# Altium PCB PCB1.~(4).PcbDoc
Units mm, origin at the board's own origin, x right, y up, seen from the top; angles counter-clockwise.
Board outline 152.4 x 101.6 mm, 2 copper layers (Top Layer, Bottom Layer); 19 components, 17 nets, 64 pads, 0 vias.
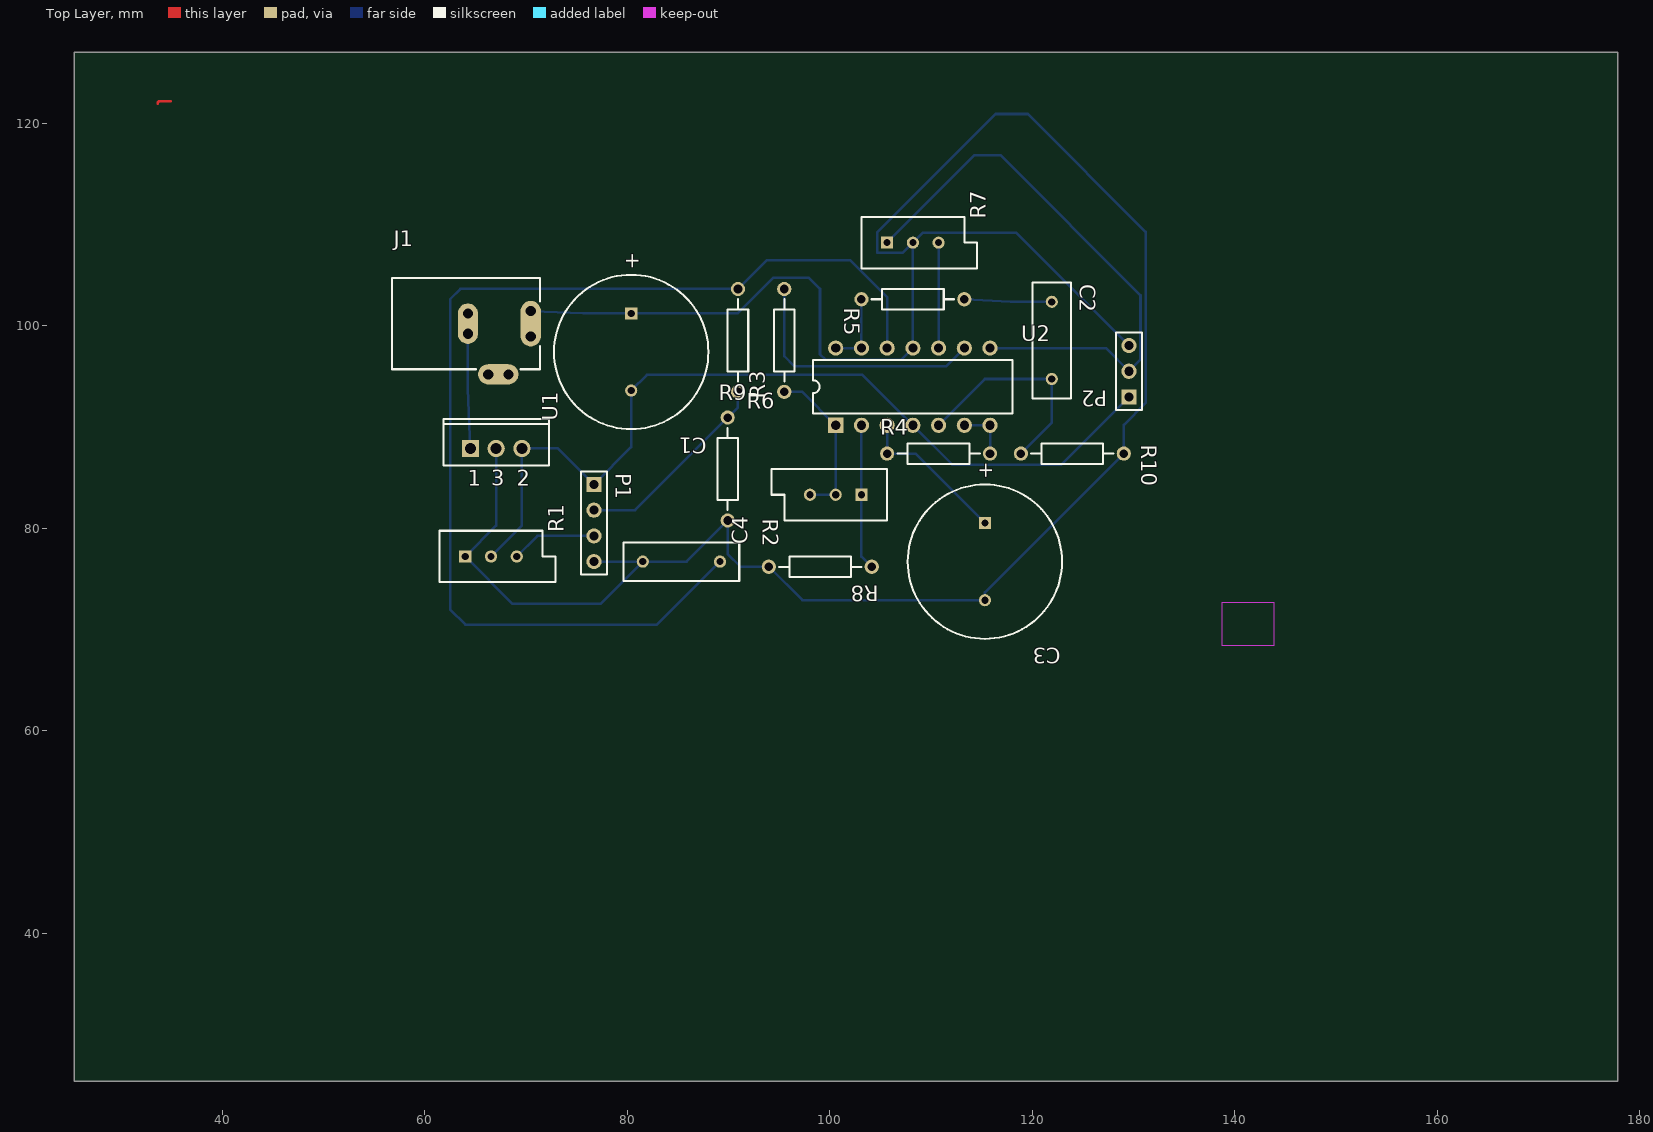
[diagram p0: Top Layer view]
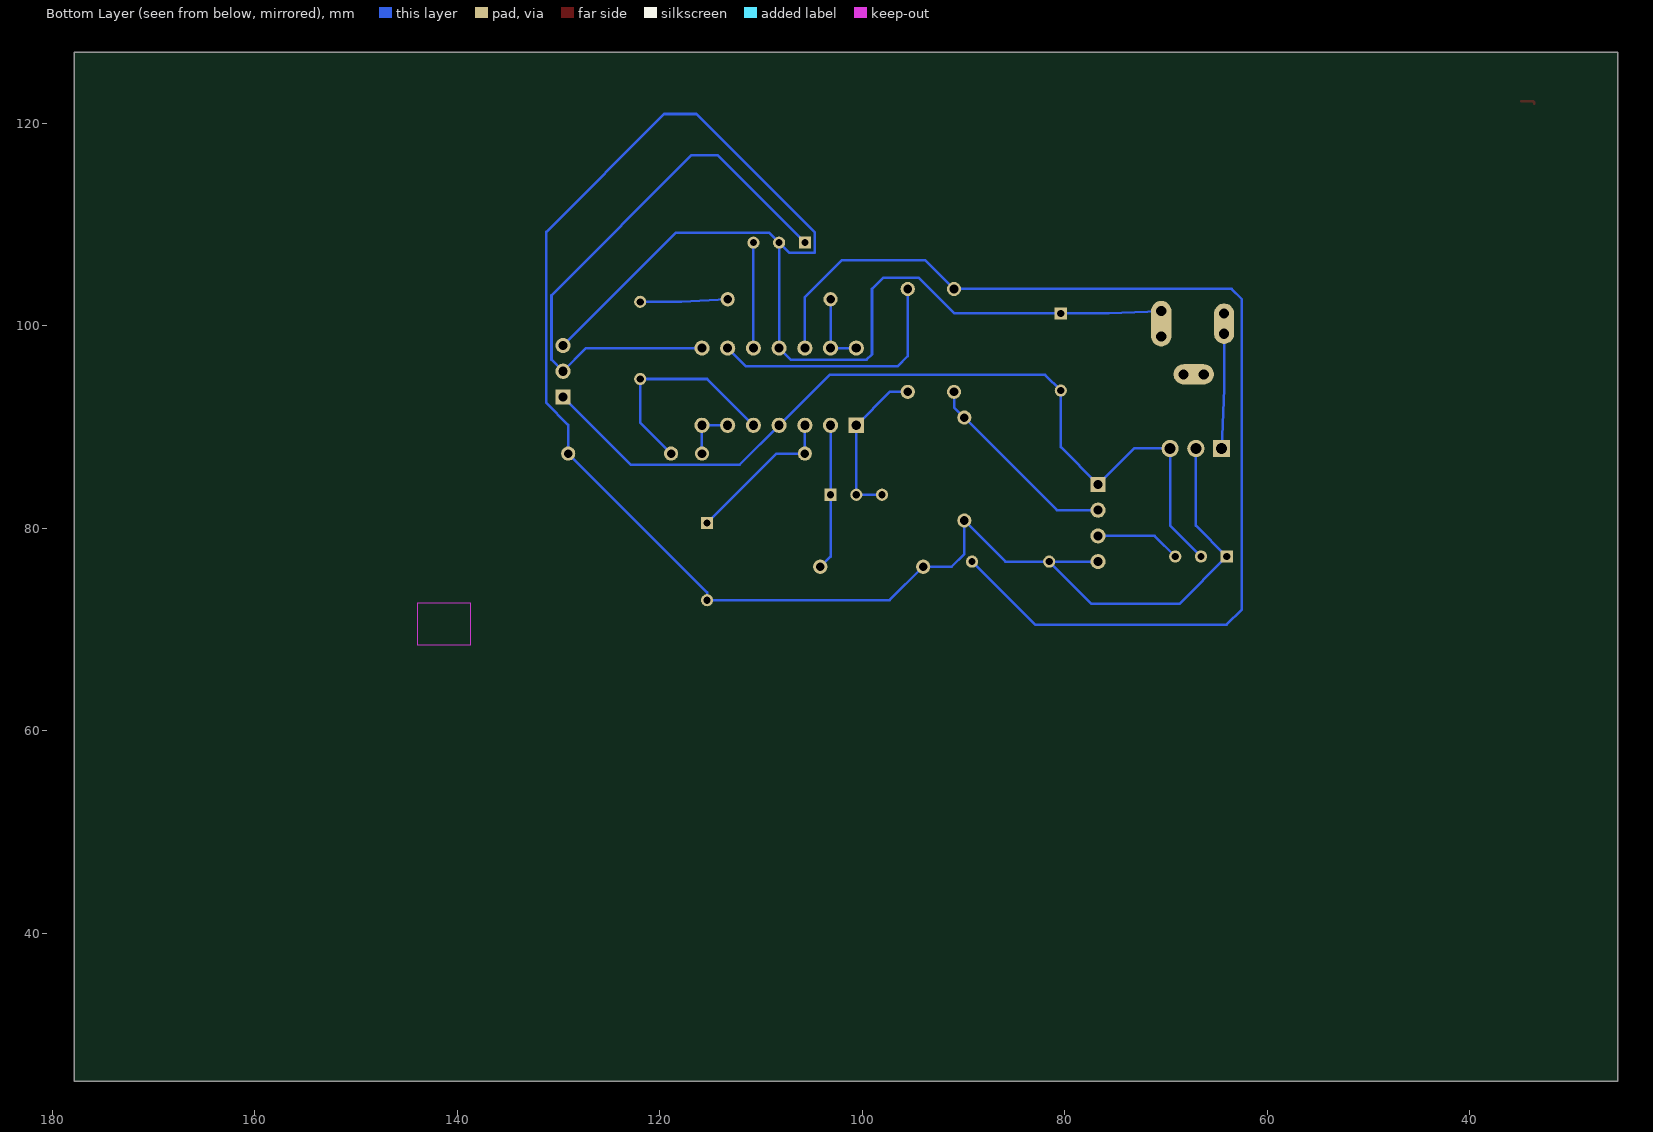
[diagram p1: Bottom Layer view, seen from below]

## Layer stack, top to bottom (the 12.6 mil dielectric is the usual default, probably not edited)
Top Layer: signal copper 0.0356
Dielectric: dielectric 0.32, FR-4, Dk 4.8
Bottom Layer: signal copper 0.0356

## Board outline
25.4,25.4 177.8,25.4 177.8,127 25.4,127

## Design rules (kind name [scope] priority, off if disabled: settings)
Clearance [All] p1: gap=0.254
ComponentClearance [All] p1: gap=0.254 collisioncheckmode=3 verticalgap=0.254
PolygonConnect [All] p1: connectstyle=Relief reliefconductorwidth=0.254 reliefentries=4 polygonreliefangle="90 Angle"
RoomDefinition Sheet1 [InComponentClass('Sheet1')] p1: confinementstyle=ConfineIn formatcopy=TRUE lockcomponents=FALSE outline 51.181,58.42 157.734,58.42 157.734,111.633 51.181,111.633
RoutingVias [All] p1: holewidth=0.711 width=1.27 viastyle="Through Hole" minholewidth=0.711 minwidth=1.27 maxholewidth=0.711 maxwidth=1.27
SolderMaskExpansion [All] p1: expansion=0.102
TestPointUsage [All] p1: valid=0 allowmultiple=FALSE
Testpoint [All] p1: side=15 testpointundercomponent=TRUE minsize=1.016 maxsize=2.54 preferedsize=1.524 minholesize=0 maxholesize=1.016 preferedholesize=0.813 testpointgrid=0.025 style=1023 order=0123456789
Width [All] p1: maxlimit=0.254 minlimit=0.254 preferedwidth=0.254
18 further rules are at their usual default settings.

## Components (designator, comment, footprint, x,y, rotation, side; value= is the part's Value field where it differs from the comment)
C1 "Cap Pol1" RB7.6-15 80.391,97.409 r90 top
C2 "Cap" RAD-0.3 121.92,98.552 r90 top
C3 "Cap Pol1" RB7.6-15 115.316,76.708 r90 top
C4 "Cap" RAD-0.3 85.344,76.708 r0 top
J1 "PWR2.5" KLD-0202 56.769,100.203 r0 top
P1 "Header 4" HDR1X4 76.708,84.328 r270 top
P2 "Header 3" HDR1X3 129.54,92.964 r90 top
R1 "RPot" VR5 66.548,77.216 r0 top
R2 "RPot" VR5 100.584,83.312 r180 top
R3 "Res2" AXIAL-0.4 95.504,98.552 r270 top
R4 "Res2" AXIAL-0.4 110.744,87.376 r0 top
R5 "Res2" AXIAL-0.4 108.204,102.616 r180 top
R6 "Res2" AXIAL-0.4 90.932,98.552 r270 top
R7 "RPot" VR5 108.204,108.204 r0 top
R8 "Res2" AXIAL-0.4 99.06,76.2 r180 top
R9 "Res2" AXIAL-0.4 89.916,85.852 r90 top
R10 "Res2" AXIAL-0.4 123.952,87.376 r0 top
U1 "L7812ABV" TO220ABN 67.056,87.884 r0 top
U2 "LM324AN" N14A 108.204,93.98 r0 top

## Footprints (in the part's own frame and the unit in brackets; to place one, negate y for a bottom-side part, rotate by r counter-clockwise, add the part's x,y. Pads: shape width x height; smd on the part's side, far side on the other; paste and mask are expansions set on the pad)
AXIAL-0.4 [mm] "Resistor; 2 Leads"
  round 1.4 hole 0.85: 1(-5.08,0) 2(5.08,0)
  silkscreen extent -4.06,-1.02 4.06,1.02
HDR1X3 [mm] "Connector; Header; 3 Position"
  rect 1.5x1.5 hole 0.9: 1(0,0)
  round 1.5 hole 0.9: 2(2.54,0) 3(5.08,0)
  silkscreen extent -1.27,-1.27 6.35,1.27
HDR1X4 [mm] "Connector; Header; 4 Position"
  rect 1.5x1.5 hole 0.9: 1(0,0)
  round 1.5 hole 0.9: 2(2.54,0) 3(5.08,0) 4(7.62,0)
  silkscreen extent -1.27,-1.27 8.89,1.27
KLD-0202 [mm] "DC Power Jack, 2.5mm, KLD Series, PCB Mount"
  oval 2x4.5 all layers, no hole: 1(13.7,0)
  round 1.5 hole 1: 1A(13.7,-1.25) 1B(13.7,1.25) 2A(7.5,-1) 2B(7.5,1) 3A(9.5,-5) 3B(11.5,-5)
  oval 2x4 all layers, no hole: 2(7.5,0)
  oval 4x2 all layers, no hole: 3(10.5,-5)
  silkscreen extent 0,-4.5 14.6,4.5
N14A [mm] "DIP; 14 Leads; Row Spacing 7.62 mm; Pitch 2.54 mm"
  rect 1.5x1.5 hole 0.9: 1(-7.62,-3.81)
  round 1.5 hole 0.9: 2(-5.08,-3.81) 3(-2.54,-3.81) 4(0,-3.81) 5(2.54,-3.81) 6(5.08,-3.81) 7(7.62,-3.81) 8(7.62,3.81) 9(5.08,3.81) 10(2.54,3.81) 11(0,3.81) 12(-2.54,3.81) 13(-5.08,3.81) 14(-7.62,3.81)
  silkscreen extent -9.85,-2.65 9.85,2.65
RAD-0.3 [mm] "Capacitor; 2 Leads"
  round 1.2 hole 0.7: 1(-3.81,0) 2(3.81,0)
  silkscreen extent -5.71,-1.91 5.71,1.91
RB7.6-15 [mm] "Polarized Capacitor (Radial); 2 Leads"
  rect 1.2x1.2 hole 0.7: 1(3.81,0)
  round 1.2 hole 0.7: 2(-3.81,0)
  silkscreen extent -7.62,-7.62 7.62,7.62
TO220ABN [mm] "TO, Thru-Hole, Vertical, Heatsink Mounted; 3 In-Line Leads; Pitch 2.54 mm; Pin sequence 1, 3, 2"
  rect 1.7x1.7 hole 1.1: 1(-2.54,0)
  round 1.7 hole 1.1: 2(2.54,0) 3(0,0)
  silkscreen extent -5.2,-1.7 5.2,2.9
VR5 [mm] "Potentiometer; 3 Leads"
  rect 1.2x1.2 hole 0.7: 1(-2.54,0)
  round 1.2 hole 0.7: 2(0,0) 3(2.54,0)
  silkscreen extent -5.08,-2.54 6.35,2.54

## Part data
C1 C3: "Polarized Capacitor (Radial)"
C2 C4: "Capacitor"
J1: "Low Voltage Power Supply Connector"
P1: "Header, 4-Pin"
P2: library part "Header 2", "Header, 2-Pin"
R1 R2 R7: "Potentiometer"
R3 R4 R5 R6 R8 R9 R10: "Resistor"
U1: "Precision 1A Regulator"
U2: "Low-Power Quad Operational Amplifier"

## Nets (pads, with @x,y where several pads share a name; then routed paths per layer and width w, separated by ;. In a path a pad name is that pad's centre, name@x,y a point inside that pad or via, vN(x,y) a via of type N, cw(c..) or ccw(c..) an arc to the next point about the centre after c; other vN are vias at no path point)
+5: C1.2 P1.1 P2.1 R1.2 U1.2 U2.4 | length 87.5
  Bottom Layer w0.254: R1.2 69.596,80.264 U1.2 73.152,87.884 P1.1 80.391,88.011 C1.2 81.94,95.148 103.226,95.148 U2.4 112.09,86.284 122.86,86.284 P2.1
GND: C1.1 C3.2 C4.1 J1.1 J1.1A J1.1B P1.4 P2.3 R1.1 R7.2 R8.2 R9.1 R10.2 U1.3 U2.11 | length 249.7
  Bottom Layer w0.254: U1.3 67.056,80.264 R1.1 68.682,72.542 77.368,72.542 C4.1 ; J1.1A J1.1 J1.1B 70.525,101.45 75.672,101.219 C1.1 90.907,101.219 94.412,104.724 97.942,104.724 99.035,103.632 99.035,97.18 99.568,96.647 107.061,96.647 U2.11 R7.2 ; P1.4 C4.1 ; P2.3 118.389,109.195 109.195,109.195 R7.2 ; C4.1 85.852,76.708 R9.1 89.916,77.47 91.186,76.2 R8.2 97.282,72.898 C3.2 115.316,73.66 R10.2 129.032,90.221 131.191,92.38 131.191,109.271 119.558,120.904 116.383,120.904 104.673,109.195 104.673,107.213 107.213,107.213 R7.2
NetC2_1: C2.1 R10.1 U2.5 | length 21.7
  Bottom Layer w0.254: U2.5 115.316,94.742 C2.1 121.92,90.424 R10.1
NetC2_2: C2.2 R5.1 | length 8.6
  Bottom Layer w0.254: R5.1 117.856,102.362 C2.2
NetC3_1: C3.1 R4.1 U2.3 | length 15.3
  Bottom Layer w0.254: U2.3 R4.1 108.458,87.376 C3.1
NetC4_2: C4.2 R6.1 U2.12 | length 111.8
  Bottom Layer w0.254: C4.2 82.931,70.485 64.008,70.485 62.509,71.984 62.509,102.616 63.525,103.632 R6.1 93.777,106.477 102.006,106.477 105.664,102.819 U2.12
NetJ1_3: J1.3 J1.3A J1.3B | length 2
  Bottom Layer w0.254: J1.3A J1.3 J1.3B
NetP1_2: P1.2 R6.2 R9.2 | length 20
  Bottom Layer w0.254: P1.2 80.772,81.788 R9.2 90.932,91.948 R6.2
NetP1_3: P1.3 R1.3 | length 8.5
  Bottom Layer w0.254: R1.3 71.12,79.248 P1.3
NetP2_2: P2.2 R7.1 U2.8 | length 57
  Bottom Layer w0.254: R7.1 114.3,116.84 116.84,116.84 130.683,102.997 130.683,96.647 P2.2 127.254,97.79 U2.8
NetR2_1: R2.1 R8.1 U2.2 | length 14.4
  Bottom Layer w0.254: U2.2 R2.1 103.124,77.216 R8.1
NetR2_2: R2.2 R2.3 R3.2 U2.1 | length 15.8
  Bottom Layer w0.254: R3.2 97.282,93.472 U2.1 R2.2 R2.3
NetR3_1: R3.1 U2.9 | length 25.6
  Bottom Layer w0.254: R3.1 95.504,97.003 96.52,95.987 111.481,95.987 U2.9
NetR4_2: R4.2 U2.6 U2.7 | length 5.3
  Bottom Layer w0.254: U2.6 U2.7 R4.2
NetR5_2: R5.2 U2.13 U2.14 | length 7.4
  Bottom Layer w0.254: U2.14 U2.13 R5.2
NetR7_3: R7.3 U2.10 | length 10.4
  Bottom Layer w0.254: U2.10 R7.3
VCC: J1.2 J1.2A J1.2B U1.1 | length 13.3
  Bottom Layer w0.254: J1.2B J1.2 J1.2A 64.269,93.77 U1.1
copper on no net: | length 1.4
  Top Layer w0.254: 33.655,121.92 33.655,122.047 33.782,122.174 34.925,122.174

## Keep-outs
Keep-Out Layer:
  rectangle: 138.684,68.453 143.891,72.644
